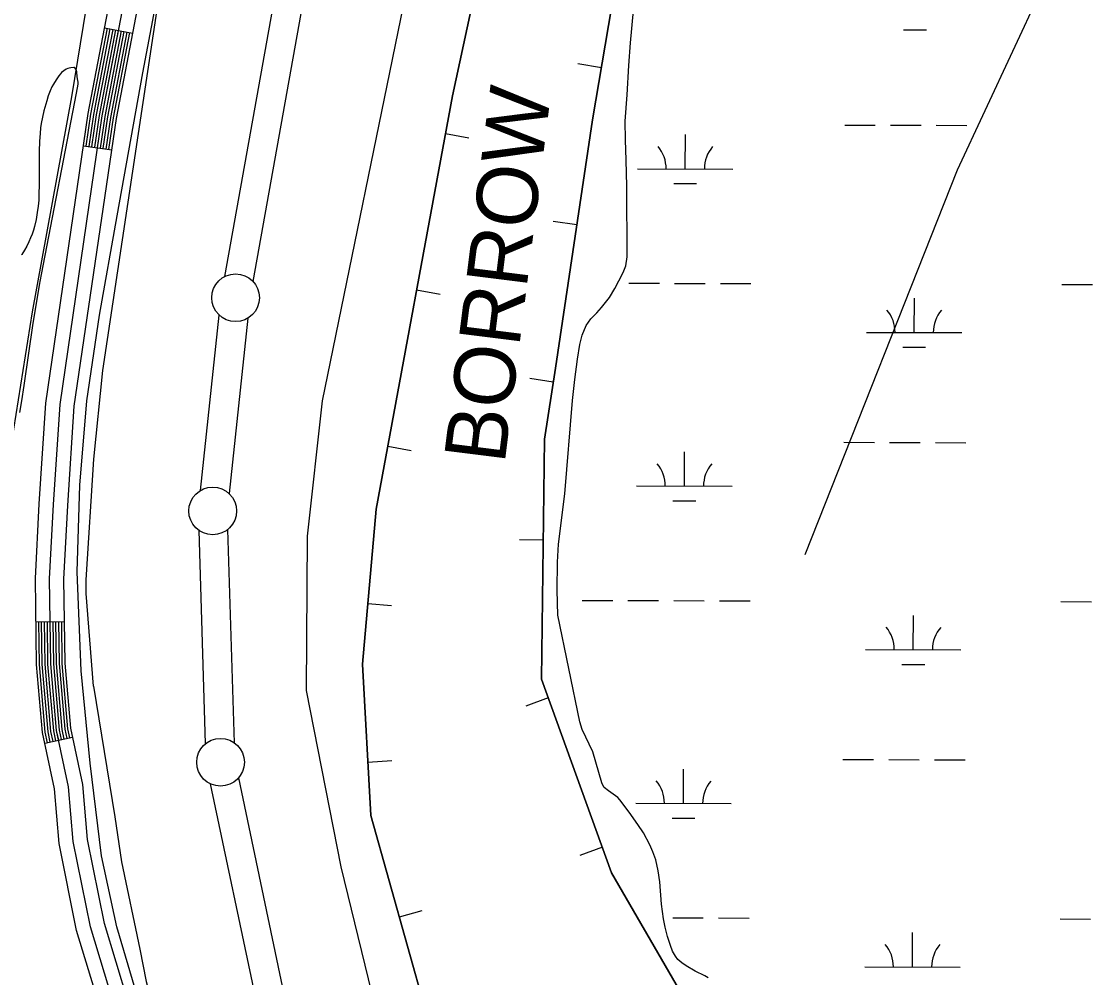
# Model space of a CAD drawing. Extents: x 3161615 to 3199515, y 867541 to 892976.
# Drawn here: x 3177115 to 3178243, y 880727 to 881729 of the extents above; entities that cross this region are included whole.
import ezdxf

# ---------------------------------------------------------------- set-up
doc = ezdxf.new("R2010")
doc.units = 0
for name, color, linetype in [('V-BORW-IDEN', 7, 'Continuous'), ('V-BORW-LINE', 7, 'Continuous'), ('V-LEVE-TOET', 7, 'Continuous'), ('V-ROAD-CNTR', 7, 'Continuous'), ('V-SITE-VEGE', 7, 'Continuous'), ('V-SURV-LINE', 7, 'Continuous'), ('V-TOPO-SHOR', 7, 'Continuous'), ('V-WETL-SWMP', 7, 'Continuous')]:
    doc.layers.add(name, color=color, linetype=linetype)

msp = doc.modelspace()

# ---------------------------------------------------------------- linework, layer by layer
at = {"layer": 'V-BORW-LINE'}
for p, q in [((3177722.4, 881680.7), (3177697.7, 881684.9)), ((3177558.9, 881611.9), (3177583.5, 881607.4)), ((3177696.6, 881516.1), (3177671.9, 881519.8)), ((3177528.6, 881448.1), (3177553.2, 881443.5)), ((3177671.9, 881351.4), (3177647.2, 881355.1)), ((3177498.4, 881284.2), (3177523, 881279.7)), ((3177661.4, 881185.5), (3177636.4, 881185.8)), ((3177477.4, 881119.1), (3177502.3, 881116.9)), ((3177666.7, 881020.1), (3177643.2, 881011.6)), ((3177477.6, 880952.9), (3177502.6, 880954.4)), ((3177723.4, 880863.5), (3177699.9, 880855)), ((3177510.6, 880790.5), (3177534.6, 880797.3))]:
    msp.add_line(p, q, dxfattribs=at)
for points in [[(3177906.6, 882507), (3177867.3, 882300.3), (3177808.7, 882150.3), (3177775.1, 881987.1), (3177749.8, 881843.1), (3177713.2, 881626.3), (3177674.2, 881366.1), (3177662.8, 881291.6), (3177659.6, 881039.8), (3177733, 880836.9), (3177872.5, 880595.9), (3177977.1, 880322), (3178056.3, 880129.2), (3178107.7, 879988.9), (3178144.8, 879887), (3178142.7, 879801.7), (3178101.3, 879712.9)], [(3178092.2, 879710.3), (3178065.6, 879669.2), (3178013.2, 879621.3), (3177941.5, 879615.1), (3177873.5, 879721.9), (3177776.5, 879970.7), (3177692.1, 880217), (3177605.2, 880463.4), (3177538.3, 880691.4), (3177480.8, 880896.9), (3177471.8, 881055.7), (3177486.2, 881218), (3177566.2, 881651.6), (3177659.6, 882084.4), (3177695.5, 882282.8), (3177716.7, 882419.5), (3177742.6, 882484.1)], [(3177742.6, 882484.1), (3177716.7, 882419.5), (3177695.5, 882282.8), (3177659.6, 882084.4), (3177566.2, 881651.6), (3177486.2, 881218), (3177471.8, 881055.7), (3177480.8, 880896.9), (3177538.3, 880691.4), (3177605.2, 880463.4), (3177692.1, 880217), (3177776.5, 879970.7), (3177873.5, 879721.9), (3177941.5, 879615.1), (3178013.2, 879621.3), (3178065.6, 879669.2), (3178100.9, 879713.6)], [(3178100.7, 879713), (3178142.7, 879801.7), (3178144.8, 879887), (3178107.7, 879988.9), (3178056.3, 880129.2), (3177977.1, 880322), (3177872.5, 880595.9), (3177733, 880836.9), (3177659.6, 881039.8), (3177662.8, 881291.6), (3177674.2, 881366.1), (3177713.2, 881626.3), (3177749.8, 881843.1), (3177765.7, 881933.1)]]:
    msp.add_lwpolyline(points, dxfattribs=at)
at = {"layer": 'V-LEVE-TOET'}
for points in [[(3177667.1, 882590.9), (3177614.2, 882321.3), (3177579.7, 882099.5), (3177517.4, 881760), (3177429.5, 881331.5), (3177414, 881189.6), (3177412.9, 881027.8)], [(3177190.1, 881032.5), (3177182.4, 881129.6), (3177182.4, 881143.9), (3177190.2, 881270.4), (3177199.9, 881363.4), (3177257.7, 881749), (3177352.5, 882264.8), (3177402.7, 882556.7)], [(3177190.1, 881032.5), (3177212.4, 880895.6), (3177219.4, 880848.2), (3177238.4, 880756.8), (3177245.2, 880722.9), (3177250.9, 880702.4), (3177266.2, 880652.8), (3177303.4, 880541.3), (3177361.3, 880352), (3177475.6, 880035.3), (3177559.5, 879716.2), (3177585.5, 879647.1), (3177608.2, 879589.3), (3177632.1, 879544), (3177652.9, 879510.5), (3177737.9, 879384.6), (3177804.7, 879295.2), (3177918.6, 879156.7), (3178101.7, 878928.5)], [(3177412.9, 881027.8), (3177449.1, 880843), (3177499.5, 880636.8), (3177577.4, 880371), (3177632.4, 880148.7), (3177689.7, 879983.7), (3177760.7, 879786.6), (3177799.6, 879676.6)]]:
    msp.add_lwpolyline(points, dxfattribs=at)
at = {"layer": 'V-ROAD-CNTR'}
for p, q in [((3177201.6, 881722.9), (3177231, 881717.2)), ((3177179.4, 881599.2), (3177209.1, 881594.9)), ((3177129.6, 881100), (3177159.6, 881100.4)), ((3177138.8, 880972.6), (3177168.1, 880978.9))]:
    msp.add_line(p, q, dxfattribs=at)
for points in [[(3177372.4, 880118.9), (3177333.6, 880246.4), (3177235.9, 880565.3), (3177197.2, 880693.8), (3177172.3, 880776.4), (3177154, 880867.6), (3177149.1, 880924.8), (3177136.4, 880983.8), (3177130.2, 881055.1), (3177129, 881145.4), (3177132.9, 881223.7), (3177140, 881329.3), (3177184.4, 881632.9), (3177269.1, 882075.3), (3177338.3, 882444.5), (3177405.5, 882803.5), (3177445.5, 883028.2)], [(3177211.6, 880698.1), (3177186.8, 880780.1), (3177168.8, 880869.7), (3177163.9, 880927), (3177151.3, 880986), (3177145.2, 881055.8), (3177144, 881145.1), (3177147.9, 881222.8), (3177154.9, 881327.7), (3177199.1, 881630.4), (3177283.8, 882072.5), (3177353.1, 882441.8), (3177420.2, 882800.8)], [(3177225.9, 880702.4), (3177201.4, 880783.7), (3177183.7, 880871.8), (3177178.8, 880929.2), (3177166.1, 880988.3), (3177160.2, 881056.6), (3177159, 881144.8), (3177162.9, 881221.9), (3177169.8, 881326.1), (3177213.9, 881627.9), (3177298.5, 882069.8), (3177367.8, 882439), (3177435, 882798.1)], [(3177182.4, 881598.8), (3177187.3, 881632.4), (3177204.5, 881722.3)], [(3177185.4, 881598.3), (3177190.3, 881631.9), (3177207.5, 881721.7)], [(3177188.3, 881597.9), (3177193.2, 881631.4), (3177210.4, 881721.2)], [(3177191.3, 881597.5), (3177196.2, 881630.9), (3177213.4, 881720.6)], [(3177194.3, 881597), (3177199.1, 881630.4), (3177216.3, 881720.1)], [(3177197.2, 881596.6), (3177202.1, 881629.9), (3177219.3, 881719.5)], [(3177200.2, 881596.2), (3177205.1, 881629.4), (3177222.2, 881718.9)], [(3177203.2, 881595.7), (3177208, 881628.9), (3177225.1, 881718.4)], [(3177206.1, 881595.3), (3177211, 881628.4), (3177228.1, 881717.8)], [(3177141.7, 880973.2), (3177139.4, 880984.2), (3177133.2, 881055.2), (3177132.6, 881100.1)], [(3177144.7, 880973.9), (3177142.4, 880984.7), (3177136.2, 881055.4), (3177135.6, 881100.1)], [(3177147.6, 880974.5), (3177145.3, 880985.1), (3177139.2, 881055.5), (3177138.6, 881100.2)], [(3177150.5, 880975.1), (3177148.3, 880985.6), (3177142.2, 881055.7), (3177141.6, 881100.2)], [(3177153.5, 880975.7), (3177151.3, 880986), (3177145.2, 881055.8), (3177144.6, 881100.2)], [(3177156.4, 880976.4), (3177154.2, 880986.5), (3177148.2, 881056), (3177147.6, 881100.3)], [(3177159.3, 880977), (3177157.2, 880986.9), (3177151.2, 881056.1), (3177150.6, 881100.3)], [(3177162.3, 880977.6), (3177160.2, 880987.4), (3177154.2, 881056.3), (3177153.6, 881100.4)], [(3177165.2, 880978.3), (3177163.2, 880987.8), (3177157.2, 881056.4), (3177156.6, 881100.4)]]:
    msp.add_lwpolyline(points, dxfattribs=at)
at = {"layer": 'V-SITE-VEGE'}
for p, q in [((3177158.7, 881677.8), (3177156.5, 881675.9)), ((3177161.2, 881679.4), (3177158.7, 881677.8)), ((3177163, 881680.1), (3177161.2, 881679.4)), ((3177164.3, 881680.5), (3177163, 881680.1)), ((3177166.3, 881680.8), (3177164.3, 881680.5)), ((3177169.5, 881681.2), (3177166.3, 881680.8)), ((3177170, 881681.1), (3177169.5, 881681.2)), ((3177170.5, 881680.7), (3177170, 881681.1)), ((3177171.4, 881679.6), (3177170.5, 881680.7)), ((3177171.9, 881678.6), (3177171.4, 881679.6)), ((3177172.4, 881676.8), (3177171.9, 881678.6)), ((3177150.7, 881668.3), (3177148, 881663.9)), ((3177153.7, 881672.5), (3177150.7, 881668.3)), ((3177155.3, 881674.5), (3177153.7, 881672.5)), ((3177156.5, 881675.9), (3177155.3, 881674.5)), ((3177172.7, 881671.4), (3177172.4, 881676.8)), ((3177173.6, 881667.6), (3177172.7, 881671.4)), ((3177173.9, 881665.7), (3177173.6, 881667.6)), ((3177144.5, 881656.8), (3177142.6, 881651.6)), ((3177146.4, 881660.9), (3177144.5, 881656.8)), ((3177148, 881663.9), (3177146.4, 881660.9)), ((3177172.3, 881654.3), (3177173.9, 881663.8)), ((3177173.9, 881663.8), (3177173.9, 881665.7)), ((3177135.4, 881464.2), (3177172.3, 881654.3)), ((3177141, 881646.4), (3177138, 881635.9)), ((3177142.6, 881651.6), (3177141, 881646.4)), ((3177138, 881635.9), (3177136.4, 881629.2)), ((3177135.2, 881622.5), (3177134.5, 881618)), ((3177136.4, 881629.2), (3177135.2, 881622.5)), ((3177133.9, 881612), (3177133.3, 881603.9)), ((3177134.5, 881618), (3177133.9, 881612)), ((3177133.3, 881603.9), (3177133, 881593.1)), ((3177133, 881593.1), (3177133.1, 881559)), ((3177133.1, 881559), (3177132.8, 881547.9)), ((3177132.8, 881547.9), (3177132.5, 881542)), ((3177131.9, 881535.7), (3177131, 881529)), ((3177132.5, 881542), (3177131.9, 881535.7)), ((3177129.8, 881521.9), (3177128, 881514.4)), ((3177131, 881529), (3177129.8, 881521.9)), ((3177126.9, 881510.5), (3177125.6, 881506.6)), ((3177128, 881514.4), (3177126.9, 881510.5)), ((3177122.2, 881498.3), (3177120.2, 881494)), ((3177124, 881502.5), (3177122.2, 881498.3)), ((3177125.6, 881506.6), (3177124, 881502.5)), ((3177117.8, 881489.6), (3177115, 881485.1)), ((3177120.2, 881494), (3177117.8, 881489.6)), ((3177115, 881485.1), (3177114.5, 881484.6)), ((3177133.4, 881452.9), (3177135.4, 881464.2)), ((3177129.8, 881431.7), (3177133.4, 881452.9)), ((3177126.8, 881413.1), (3177129.8, 881431.7)), ((3177117.3, 881347.9), (3177126.8, 881413.1)), ((3177114.7, 881331.6), (3177117.3, 881347.9)), ((3177112.7, 881319.5), (3177114.7, 881331.6))]:
    msp.add_line(p, q, dxfattribs=at)
for points in [[(3177751.1, 881683.2), (3177753, 881707), (3177756, 881740.9)], [(3177834.2, 880726.5), (3177830.9, 880728.6), (3177820.6, 880733.7), (3177811.3, 880739.2), (3177806.8, 880742.3), (3177802.5, 880746), (3177799.9, 880749.2), (3177797, 880754.7), (3177794.8, 880760.6), (3177791.7, 880770.1), (3177789.1, 880779.7), (3177787.3, 880788.4), (3177785.5, 880803.8), (3177783.6, 880827.2), (3177782, 880838.7), (3177779.3, 880850.2), (3177776.3, 880858.9), (3177773.1, 880866.2), (3177766.4, 880878.6), (3177760.7, 880887.5), (3177751.5, 880900.5), (3177741.8, 880913.2), (3177739.6, 880915.7), (3177729.7, 880922.6), (3177725.4, 880926.3), (3177723.8, 880928.5), (3177722.7, 880931), (3177713.3, 880963.5), (3177702.3, 880987.1), (3177699.6, 880995.1), (3177676.7, 881106.9), (3177676.1, 881133.1), (3177676.2, 881162.5), (3177677.4, 881181.2), (3177684.1, 881234), (3177692, 881332), (3177694.4, 881354.2), (3177697.3, 881375.4), (3177699.8, 881390.6), (3177702.3, 881400.5), (3177706.4, 881410.5), (3177711.4, 881417.6), (3177717.4, 881423.9), (3177722.4, 881429.5), (3177730.8, 881440.2), (3177736.4, 881449.4), (3177740.5, 881457.6), (3177745.3, 881466.1), (3177747.9, 881473.4), (3177749.5, 881482.8), (3177749.1, 881556.6), (3177748.2, 881584.1), (3177747.7, 881605.2), (3177747.3, 881625), (3177749.3, 881652.4), (3177751.1, 881683.2)]]:
    msp.add_lwpolyline(points, dxfattribs=at)
at = {"layer": 'V-SURV-LINE'}
for points in [[(3177327.6, 881462.1), (3177693.3, 883505.7)], [(3177722.8, 883500.4), (3177357.1, 881456.8)], [(3177302.1, 881237.7), (3177321.8, 881421.6)], [(3177351.6, 881418.4), (3177332, 881234.5)], [(3177307.5, 880972.2), (3177300.6, 881195.8)], [(3177330.5, 881196.7), (3177337.5, 880973.2)], [(3177341.9, 880936.2), (3177389.6, 880709.6)], [(3177360.3, 880703.4), (3177312.6, 880930)]]:
    msp.add_lwpolyline(points, dxfattribs=at)
for centre in [(3177338.9, 881439.8), (3177314.9, 881216.2), (3177323.1, 880952.7)]:
    msp.add_circle(centre, 25, dxfattribs=at)
at = {"layer": 'V-TOPO-SHOR'}
for points in [[(3177241.5, 881675.7), (3177367.8, 882341.2), (3177460.8, 882841.3), (3177532.3, 883225.1), (3177553.8, 883351.9), (3177571.7, 883462.8), (3177580.9, 883584.4), (3177586.4, 883679.5), (3177585.4, 883963.1), (3177585.9, 884135.7), (3177589.2, 884674.8), (3177595.1, 884924.9)], [(3177935.9, 881170.6), (3178095.6, 881573.8), (3178182.6, 881760.9), (3178269.5, 881919.2), (3178342, 882048.8), (3178356.5, 882092), (3178443.2, 882178.2), (3178515.5, 882250.1), (3178573.4, 882336.4), (3178674.7, 882480.3), (3178775.8, 882566.5), (3178920.3, 882667), (3178978.1, 882738.9), (3179079.4, 882868.4), (3179093.8, 882868.3), (3179166, 882911.4), (3179199.4, 882919.6)], [(3177263.6, 882233.2), (3177200.9, 881858.1), (3177166.8, 881650.3), (3177125.7, 881424.9), (3177098.8, 881255.9), (3177082.7, 881159)], [(3177447.3, 880018.1), (3177398.5, 880177), (3177326.7, 880407.6), (3177263.5, 880611), (3177235.4, 880709), (3177214.3, 880780.1), (3177198.2, 880854.5), (3177186.5, 880951.7), (3177177.1, 881048.6), (3177172.9, 881152.5), (3177175.7, 881243.1), (3177182.8, 881331.7), (3177196.1, 881421.5), (3177214.6, 881525.5), (3177241.5, 881675.7)]]:
    msp.add_lwpolyline(points, dxfattribs=at)
at = {"layer": 'V-WETL-SWMP'}
for p, q in [((3178039.1, 881720.7), (3178063.1, 881720.6)), ((3177810.3, 881574.9), (3177810.4, 881610.9)), ((3177977.4, 881620.9), (3178009.4, 881620.8)), ((3178025.4, 881620.7), (3178057.4, 881620.6)), ((3178073.4, 881620.6), (3178105.4, 881620.5)), ((3177760.3, 881575), (3177860.3, 881574.7)), ((3177798.2, 881559.5), (3177822.2, 881559.4)), ((3177751.1, 881455), (3177783.1, 881454.9)), ((3177799.1, 881454.8), (3177831.1, 881454.8)), ((3177847.1, 881454.7), (3177879.1, 881454.6)), ((3178205, 881453.7), (3178237, 881453.6)), ((3178050.3, 881403.4), (3178050.4, 881439.4)), ((3178000.3, 881403.5), (3178100.3, 881403.3)), ((3178038.2, 881388), (3178062.2, 881387.9)), ((3177976.5, 881288.2), (3178008.5, 881288.1)), ((3178024.5, 881288), (3178056.5, 881288)), ((3178072.5, 881287.9), (3178104.5, 881287.8)), ((3177809.3, 881242.2), (3177809.4, 881278.2)), ((3177759.3, 881242.4), (3177859.3, 881242.1)), ((3177797.3, 881226.8), (3177821.3, 881226.7)), ((3177702.2, 881122.4), (3177734.2, 881122.3)), ((3177750.2, 881122.3), (3177782.2, 881122.2)), ((3177798.2, 881122.2), (3177830.2, 881122.1)), ((3177846.2, 881122), (3177878.2, 881122)), ((3178204.1, 881121.1), (3178236.1, 881121)), ((3178049.3, 881070.7), (3178049.4, 881106.7)), ((3177999.3, 881070.9), (3178099.3, 881070.6)), ((3178037.3, 881055.3), (3178061.3, 881055.3)), ((3177975.6, 880955.5), (3178007.6, 880955.4)), ((3178023.6, 880955.4), (3178055.6, 880955.3)), ((3178071.6, 880955.2), (3178103.6, 880955.2)), ((3177808.4, 880909.5), (3177808.5, 880945.5)), ((3177758.4, 880909.7), (3177858.4, 880909.4)), ((3177796.4, 880894.1), (3177820.4, 880894.1)), ((3177797.2, 880789.5), (3177829.2, 880789.4)), ((3177845.2, 880789.4), (3177877.2, 880789.3)), ((3178203.1, 880788.4), (3178235.1, 880788.3)), ((3178048.4, 880738.1), (3178048.5, 880774.1)), ((3177998.4, 880738.2), (3178098.4, 880737.9))]:
    msp.add_line(p, q, dxfattribs=at)
for points in [[(3177783.6, 880827.2), (3177782, 880838.7), (3177779.3, 880850.2), (3177776.3, 880858.9), (3177773.1, 880866.2), (3177766.4, 880878.6), (3177760.7, 880887.5), (3177751.5, 880900.5), (3177741.8, 880913.2), (3177739.6, 880915.7), (3177729.7, 880922.6), (3177725.4, 880926.3), (3177723.8, 880928.5), (3177722.7, 880931), (3177713.3, 880963.5), (3177702.3, 880987.1), (3177699.6, 880995.1), (3177676.7, 881106.9), (3177676.1, 881133.1), (3177676.2, 881162.5), (3177677.4, 881181.2), (3177684.1, 881234), (3177692, 881332), (3177694.4, 881354.2), (3177697.3, 881375.4), (3177699.8, 881390.6), (3177702.3, 881400.5), (3177706.4, 881410.5), (3177711.4, 881417.6), (3177717.4, 881423.9), (3177722.4, 881429.5), (3177730.8, 881440.2), (3177736.4, 881449.4), (3177740.5, 881457.6), (3177745.3, 881466.1), (3177747.9, 881473.4), (3177749.5, 881482.8), (3177749.1, 881556.6), (3177748.2, 881584.1), (3177747.7, 881605.2), (3177747.3, 881625), (3177749.3, 881652.4), (3177751.1, 881683.2), (3177753, 881707), (3177756, 881740.9)], [(3177834.2, 880726.5), (3177830.9, 880728.6), (3177820.6, 880733.7), (3177811.3, 880739.2), (3177806.8, 880742.3), (3177802.5, 880746), (3177799.9, 880749.2), (3177797, 880754.7), (3177794.8, 880760.6), (3177791.7, 880770.1), (3177789.1, 880779.7), (3177787.3, 880788.4), (3177785.5, 880803.8), (3177783.6, 880827.2)]]:
    msp.add_lwpolyline(points, dxfattribs=at)
for centre, start, end in [((3177755, 881575.5), 359.0699, 40.6135), ((3177865.5, 881575.2), 139.0699, 180.6135), ((3177995, 881404), 359.0699, 40.6135), ((3178105.5, 881403.7), 139.0699, 180.6135), ((3177754.1, 881242.8), 359.0699, 40.6135), ((3177864.6, 881242.5), 139.0699, 180.6135), ((3177994.1, 881071.4), 359.0699, 40.6135), ((3178104.6, 881071.1), 139.0699, 180.6135), ((3177753.2, 880910.2), 359.0699, 40.6135), ((3177863.7, 880909.9), 139.0699, 180.6135), ((3177993.2, 880738.7), 359.0699, 40.6135), ((3178103.7, 880738.4), 139.0699, 180.6135)]:
    msp.add_arc(centre, 35.2, start, end, dxfattribs=at)

# ---------------------------------------------------------------- texts
at = {"layer": 'V-BORW-IDEN'}
msp.add_text('BORROW', height=64, rotation=82.8749, dxfattribs=at).set_placement((3177620.8, 881264.5))

doc.saveas('drawing.dxf')
